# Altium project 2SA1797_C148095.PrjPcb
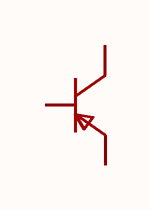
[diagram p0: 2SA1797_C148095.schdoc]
1 sheet, 1 parts. Net scope: global (net labels, ports and power ports of the same name join across sheets).

## Sheet 2SA1797_C148095.schdoc
size 127 x 101 mm

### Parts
Q?  2sa1797(range:180-390)  [SOT-89_L4.5-W2.5-P1.50-LS4.2-BR]  (value not drawn)

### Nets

Not connected (* = marked no-connect by the designer): Q? 1(B) 2(C) 3(E)

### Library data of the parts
Q? = 2sa1797(range:180-390): 晶体管类型:PNP;集电极电流(Ic):2A;集射极击穿电压(Vceo):50V;耗散功率(Pd):500mW;直流电流增益(hFE):82;; Manufacturer: CJ(江苏长电/长晶); Symbol: 2SA1797_C148095; AddInBom: yes; ModelId: 6db690b7897d4d18a30d90c1b89525ee; ModelName: SOT-89-3_L4.3-W2.5-H1.6-LS4.1-P1.50; ModelTransform: 161.417,169.291,0,180,0,0,-18.504,-0.005,0; type: PNP; Current - Collector(Ic): 2A; Collector - Emitter Voltage VCEO: 50V; Pd - Power Dissipation: 500mW; DC Current Gain: 82; Transition frequency(fT): 200MHz; Current - Collector Cutoff: 100nA; Vce Saturation(VCE(sat)): 350mV; Emitter-Base Voltage(Vebo): 6V; Number: 1个PNP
